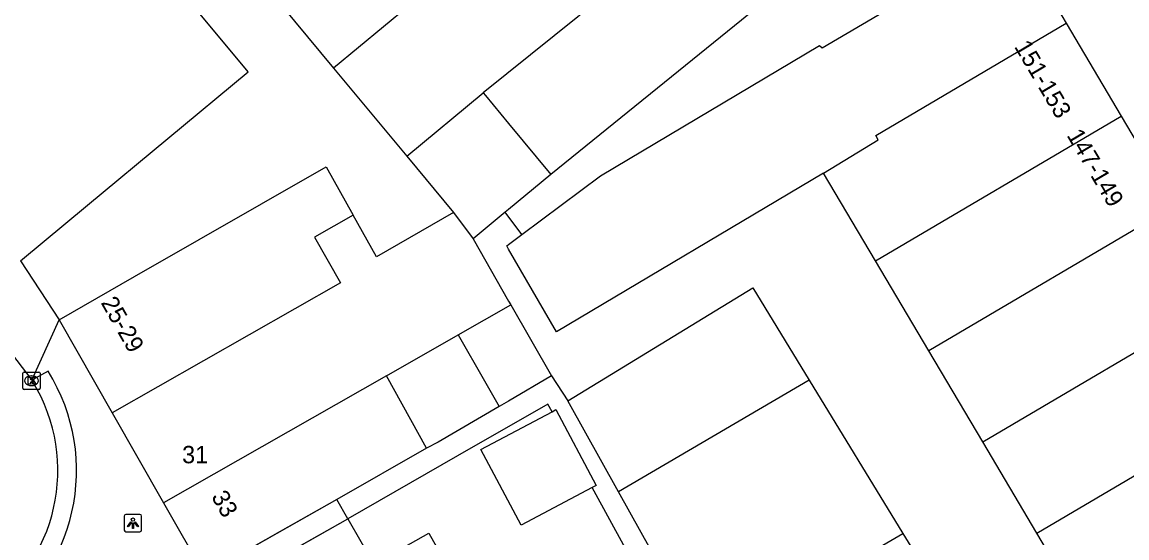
# Model space of a CAD drawing. Extents: x 160379 to 161131, y 383940 to 384849.
# Drawn here: x 160972 to 161035.5, y 384440 to 384469.7 of the extents above; entities that cross this region are included whole.
import ezdxf

# ---------------------------------------------------------------- set-up
doc = ezdxf.new("R2010")
doc.units = 0
for name, color, linetype in [('IMGEO_Kolk', 7, 'Continuous'), ('IMGEO_Lichtpunt', 7, 'Continuous'), ('IMGEO_Pand', 7, 'Continuous'), ('IMGEO_Pand_nummerreeks', 7, 'Continuous'), ('IMGEO_Pand_overbouw', 7, 'Continuous'), ('IMGEO_Rijbaan_lokaal_open', 7, 'Continuous'), ('IMGEO_Voetpad_open', 7, 'Continuous')]:
    doc.layers.add(name, color=color, linetype=linetype)

msp = doc.modelspace()

# ---------------------------------------------------------------- linework, layer by layer
at = {"layer": 'IMGEO_Kolk'}
for p, q in [((160972.073, 384448.622), (160972.073, 384449.474)), ((160972.148, 384449.548), (160973, 384449.548)), ((160972.561, 384449.328), (160972.586, 384449.328)), ((160973.074, 384449.474), (160973.074, 384448.622)), ((160973, 384448.548), (160972.148, 384448.548)), ((160972.584, 384448.768), (160972.559, 384448.768))]:
    msp.add_line(p, q, dxfattribs=at)
for points in [[(160972.073, 384448.622), (160972.073, 384449.474)], [(160972.148, 384449.548), (160973, 384449.548)], [(160972.394, 384449.248), (160972.517, 384449.248), (160972.517, 384449.097), (160972.647, 384449.248), (160972.811, 384449.248), (160972.665, 384449.097), (160972.818, 384448.848), (160972.666, 384448.848), (160972.581, 384449.012), (160972.517, 384448.945), (160972.517, 384448.848), (160972.394, 384448.848), (160972.394, 384449.248)], [(160973.074, 384449.474), (160973.074, 384448.622)], [(160973, 384448.548), (160972.148, 384448.548)]]:
    msp.add_lwpolyline(points, dxfattribs=at)
for centre, start, end in [((160972.15, 384449.472), 91.55205, 178.44795), ((160972.15, 384449.472), 91.55205, 178.44795), ((160972.998, 384449.472), 1.55205, 88.44795), ((160972.998, 384449.472), 1.55205, 88.44795), ((160972.15, 384448.624), 181.55205, 268.44795), ((160972.15, 384448.624), 181.55205, 268.44795), ((160972.998, 384448.624), 271.55205, 358.44795), ((160972.998, 384448.624), 271.55205, 358.44795)]:
    msp.add_arc(centre, 0.0765, start, end, dxfattribs=at)
for centre, major_axis, ratio, start_param, end_param in [((160972.56, 384449.048), (-0.387, 0.002), 0.722429, 4.712389, 7.853982), ((160972.585, 384449.048), (-0.39, 0.002), 0.717154, 1.570796, 4.712389)]:
    msp.add_ellipse(centre, major_axis=major_axis, ratio=ratio, start_param=start_param, end_param=end_param, dxfattribs=at)
at = {"layer": 'IMGEO_Lichtpunt'}
for p, q in [((160977.908, 384441.265), (160977.908, 384440.458)), ((160977.908, 384441.265), (160977.908, 384440.458)), ((160978.81, 384441.36), (160978.002, 384441.36)), ((160978.81, 384441.36), (160978.002, 384441.36)), ((160978.904, 384440.458), (160978.904, 384441.265)), ((160978.904, 384440.458), (160978.904, 384441.265)), ((160978.002, 384440.364), (160978.81, 384440.364)), ((160978.002, 384440.364), (160978.81, 384440.364))]:
    msp.add_line(p, q, dxfattribs=at)
for points in [[(160978.282, 384440.929), (160978.321, 384440.901), (160978.133, 384440.639), (160978.095, 384440.666), (160978.282, 384440.929)], [(160978.384, 384440.881), (160978.431, 384440.881), (160978.431, 384440.559), (160978.384, 384440.559), (160978.384, 384440.881)], [(160978.494, 384440.901), (160978.532, 384440.928), (160978.719, 384440.666), (160978.68, 384440.638), (160978.494, 384440.901)]]:
    msp.add_lwpolyline(points, dxfattribs=at)
msp.add_circle((160978.407, 384441.063), 0.0994, dxfattribs=at)
for centre, start, end in [((160978.002, 384441.265), 90, 180), ((160978.002, 384441.265), 90, 180), ((160978.81, 384441.265), 0, 90), ((160978.81, 384441.265), 0, 90), ((160978.002, 384440.458), 180, 270), ((160978.002, 384440.458), 180, 270), ((160978.81, 384440.458), 270, 0), ((160978.81, 384440.458), 270, 360)]:
    msp.add_arc(centre, 0.0946, start, end, dxfattribs=at)
at = {"layer": 'IMGEO_Pand'}
for points in [[(160971.944, 384455.948), (160975.793, 384459.141), (160985.034, 384466.802), (160963.77, 384492.344)], [(161018.068, 384491.919), (161012.403, 384487.106), (161013.117, 384486.245), (161000, 384475.366), (160989.943, 384467.026)], [(161022.376, 384485.373), (161009.387, 384474.596), (161009.515, 384474.441), (160998.539, 384465.596)], [(161025.861, 384480.076), (161015.892, 384471.854), (161013.384, 384469.774), (161002.427, 384460.908)], [(161000.762, 384457.452), (161005.273, 384460.837), (161017.867, 384468.317), (161018.016, 384468.181), (161029.052, 384474.686)], [(161029.052, 384474.686), (161032.057, 384469.602)], [(160984.712, 384473.335), (160989.943, 384467.026)], [(161018.102, 384460.989), (161021.247, 384462.908), (161021.107, 384463.147), (161032.057, 384469.602)], [(161032.057, 384469.602), (161035.213, 384464.264)], [(160989.943, 384467.026), (160994.149, 384461.954)], [(160994.149, 384461.954), (160998.539, 384465.596)], [(160998.539, 384465.596), (160998.665, 384465.445), (161000, 384463.835), (161002.427, 384460.908)], [(161021.093, 384455.939), (161035.213, 384464.264)], [(161035.213, 384464.264), (161038.277, 384459.081)], [(160994.149, 384461.954), (160996.837, 384458.712)], [(160974.165, 384452.55), (160978.505, 384455.034), (160989.518, 384461.338), (160991.072, 384458.565)], [(161002.427, 384460.908), (161000, 384458.896), (160999.808, 384458.737)], [(161018.102, 384460.989), (161002.748, 384451.85), (161000, 384456.619), (160999.895, 384456.801), (161000, 384456.88), (161000.762, 384457.452)], [(161021.093, 384455.939), (161018.102, 384460.989)], [(160996.837, 384458.712), (160992.41, 384456.178), (160991.072, 384458.565)], [(160996.837, 384458.712), (160997.955, 384457.2)], [(160999.808, 384458.737), (160997.955, 384457.2)], [(161000.762, 384457.452), (160999.808, 384458.737)], [(161038.277, 384459.081), (161024.16, 384450.76)], [(160991.072, 384458.565), (160988.84, 384457.293), (160990.335, 384454.672), (160977.221, 384447.193)], [(160997.955, 384457.2), (161000, 384453.631), (161000.131, 384453.402)], [(161024.16, 384450.76), (161021.093, 384455.939)], [(161003.403, 384447.882), (161014.043, 384454.384), (161017.283, 384449.083)], [(161027.259, 384445.528), (161041.371, 384453.848)], [(160997.106, 384451.678), (161000.131, 384453.402)], [(161000.131, 384453.402), (161002.468, 384449.324)], [(160974.165, 384452.55), (160977.221, 384447.193)], [(160992.978, 384449.323), (160997.106, 384451.678)], [(160997.106, 384451.678), (160998.617, 384449.043), (160999.466, 384447.563)], [(161027.259, 384445.528), (161024.16, 384450.76)], [(160992.978, 384449.323), (160980.171, 384442.022)], [(160995.289, 384445.161), (160992.978, 384449.323)], [(161002.468, 384449.324), (161000, 384447.876), (160999.466, 384447.563)], [(161017.283, 384449.083), (161006.312, 384442.666)], [(161017.283, 384449.083), (161022.668, 384440.27)], [(161030.369, 384440.277), (161044.477, 384448.594)], [(161006.312, 384442.666), (161003.403, 384447.882)], [(161004.798, 384442.903), (161000.727, 384440.736), (160998.409, 384445.087), (161002.495, 384447.263)], [(161002.495, 384447.263), (161002.722, 384447.384), (161005.04, 384443.032), (161004.798, 384442.903)], [(160977.221, 384447.193), (160980.171, 384442.022)], [(161030.369, 384440.277), (161027.259, 384445.528)], [(160995.289, 384445.161), (160990.127, 384442.226), (160986.869, 384440.373), (160982.522, 384437.901)], [(161011.342, 384433.645), (161006.312, 384442.666)], [(160980.171, 384442.022), (160982.522, 384437.901)], [(160983.157, 384436.79), (160987.504, 384439.262), (160990.76, 384441.113)], [(160990.76, 384441.113), (160992.256, 384438.502), (160995.407, 384440.281), (160996.559, 384438.24), (160996.664, 384438.054)], [(161011.342, 384433.645), (161022.668, 384440.27)], [(161022.668, 384440.27), (161025.2, 384436.127)], [(161033.528, 384434.943), (161030.369, 384440.277)]]:
    msp.add_lwpolyline(points, dxfattribs=at)
at = {"layer": 'IMGEO_Pand_overbouw'}
msp.add_lwpolyline([(160990.76, 384441.113), (160990.124, 384442.224), (160982.522, 384437.901), (160983.157, 384436.79)], close=True, dxfattribs=at)
at = {"layer": 'IMGEO_Rijbaan_lokaal_open'}
for points in [[(160965.518, 384457.644), (160969.312, 384453.303), (160970.863, 384451.348), (160972.595, 384449.078)], [(160971.944, 384455.948), (160974.165, 384452.55)], [(160972.595, 384449.078), (160972.659, 384448.974)]]:
    msp.add_lwpolyline(points, dxfattribs=at)
msp.add_arc((160964.331, 384443.885), 9.76, 302.99487, 31.42981, dxfattribs=at)
at = {"layer": 'IMGEO_Voetpad_open'}
for points in [[(160972.595, 384449.078), (160974.165, 384452.55)], [(160973.529, 384449.602), (160972.595, 384449.078)], [(161002.468, 384449.324), (161003.403, 384447.882)], [(161002.495, 384447.263), (161002.248, 384447.694), (160997.062, 384444.723), (160990.76, 384441.113)], [(160999.466, 384447.563), (160995.961, 384445.505), (160995.954, 384445.518), (160995.289, 384445.161)], [(161035.154, 384385.234), (161034.615, 384386.469), (161029.307, 384398.62), (161028.47, 384400.535), (161019.655, 384418.936), (161015.953, 384422.487), (161004.798, 384442.903)]]:
    msp.add_lwpolyline(points, dxfattribs=at)
msp.add_arc((160964.344, 384443.883), 10.82, 302.76721, 31.9092, dxfattribs=at)

# ---------------------------------------------------------------- texts
at = {"layer": 'IMGEO_Pand_nummerreeks'}
for s, rotation, p in [('151-153', 300.59185, (161029.039, 384468.263)), ('147-149', 300.59185, (161032.054, 384463.162)), ('25-29', 299.61481, (160976.538, 384453.537)), ('33', 299.57784, (160982.886, 384442.382))]:
    msp.add_text(s, height=1, rotation=rotation, dxfattribs=at).set_placement(p)
msp.add_text('31', height=1, dxfattribs=at).set_placement((160981.237, 384444.3))

doc.saveas('drawing.dxf')
